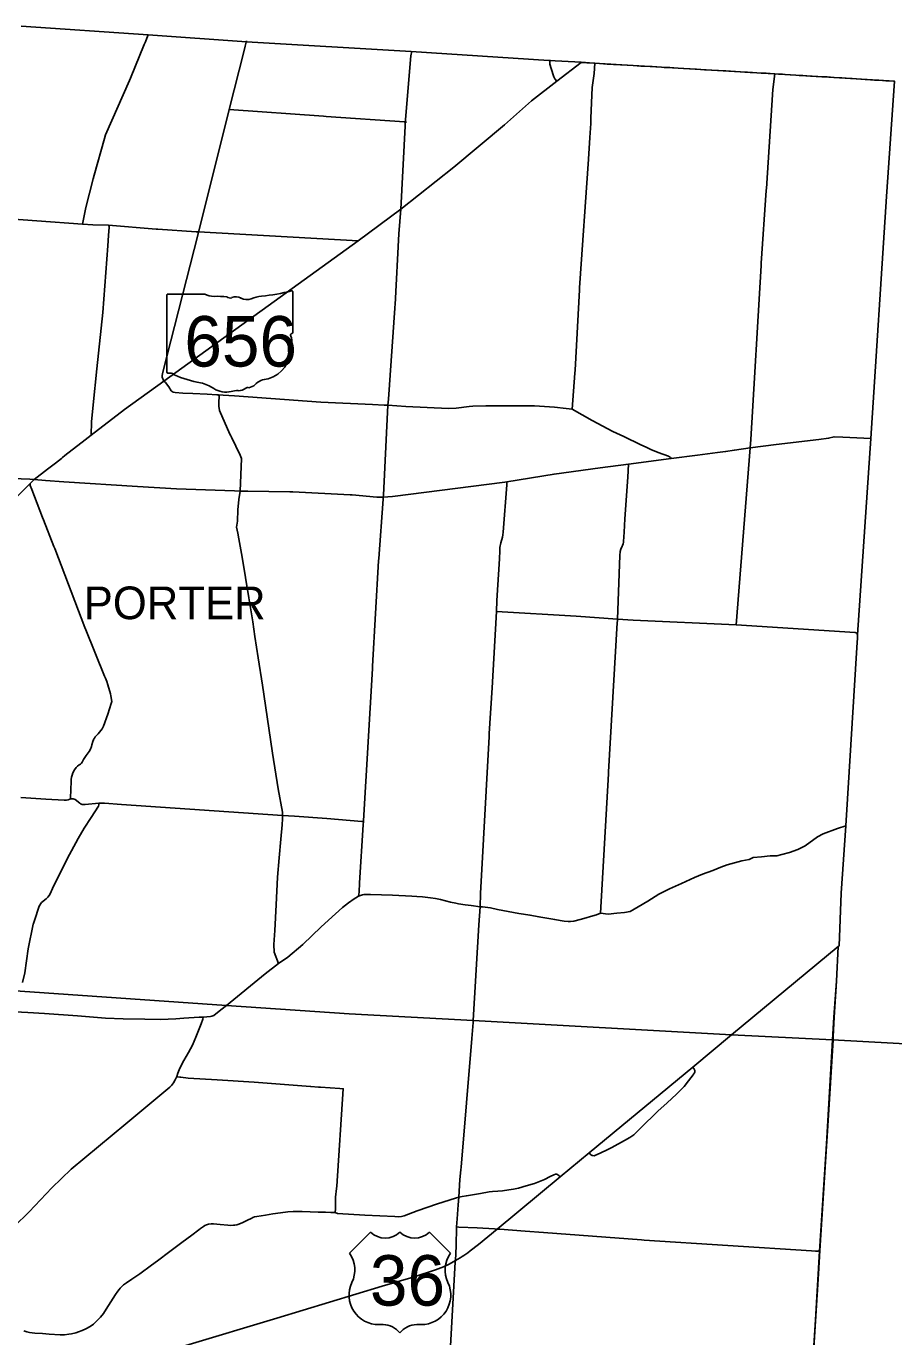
# Model space of a CAD drawing. Extents: x 1729596 to 1925846, y 659247 to 911751.
# Drawn here: x 1876281 to 1900207, y 821273 to 857428 of the extents above; entities that cross this region are included whole.
import ezdxf

# ---------------------------------------------------------------- set-up
doc = ezdxf.new("R2010")
doc.units = 0
for name, color, linetype in [('GM_X_Adjacent_County', 7, 'Continuous'), ('GM_X_County', 7, 'Continuous'), ('GM_X_County_Road', 7, 'Continuous'), ('GM_X_State_Route', 7, 'Continuous'), ('GM_X_State_Shield', 7, 'Continuous'), ('GM_X_Township', 7, 'Continuous'), ('GM_X_Township_Road', 7, 'Continuous'), ('GM_X_Township_Text', 7, 'Continuous'), ('GM_X_US_Route', 7, 'Continuous'), ('GM_X_US_Shield', 7, 'Continuous')]:
    doc.layers.add(name, color=color, linetype=linetype)

msp = doc.modelspace()

# ---------------------------------------------------------------- linework, layer by layer
at = {"layer": 'GM_X_Adjacent_County'}
msp.add_line((1898513, 829466), (1915254, 828516), dxfattribs=at)
at = {"layer": 'GM_X_County'}
msp.add_lwpolyline([(1876143, 857428), (1879641, 857188), (1882352, 856998), (1886895, 856734), (1890695, 856480), (1891588, 856432), (1891937, 856405), (1896895, 856116), (1900228, 855908), (1900008, 852727), (1899571, 846055), (1899210, 840637), (1899208, 840537), (1899202, 840435), (1898887, 835373), (1898754, 833509), (1898698, 832056), (1898677, 832037), (1898625, 831088), (1898557, 830092), (1898513, 829466), (1898352, 826597), (1898155, 823638), (1898045, 821739), (1897825, 818330)], dxfattribs=at)
at = {"layer": 'GM_X_County_Road'}
for points in [[(1878069, 846144), (1878085, 846512), (1878125, 846983), (1878226, 847978), (1878395, 849532), (1878536, 851373), (1878554, 851651), (1878570, 851880), (1878570, 851906), (1878562, 851922), (1878551, 851936), (1878115, 851952), (1877831, 851971), (1877925, 852422), (1878131, 853220), (1878152, 853318), (1878443, 854333), (1878470, 854429), (1879125, 855929), (1879153, 855993), (1879536, 856921), (1879568, 856998), (1879605, 857097), (1879641, 857189)], [(1886129, 844439), (1886132, 844491), (1886249, 846785), (1886257, 846969), (1886270, 847136), (1886449, 849651), (1886451, 849675), (1886456, 849754), (1886558, 851700), (1886613, 852377)], [(1876497, 844924), (1876809, 844899), (1877320, 844863), (1879351, 844730), (1880430, 844669), (1882026, 844608), (1882181, 844601), (1882392, 844602), (1883554, 844583), (1883632, 844581), (1885215, 844502), (1885270, 844499), (1885954, 844440), (1886129, 844439), (1886387, 844458), (1889478, 844848), (1889539, 844855), (1890840, 845073), (1892109, 845243), (1892893, 845346), (1894066, 845501), (1894790, 845594), (1895349, 845664), (1895569, 845695), (1895814, 845736), (1896247, 845793), (1896967, 845887), (1898141, 846028), (1898411, 846062), (1898560, 846100), (1898798, 846088), (1899571, 846055)], [(1883352, 835653), (1883345, 835749), (1883225, 836391), (1883075, 837371), (1882925, 838372), (1882793, 839248), (1882676, 839999), (1882590, 840590), (1882528, 840993), (1882422, 841658), (1882235, 842776), (1882147, 843282), (1882115, 843443), (1882081, 843608), (1882104, 843778), (1882120, 844088), (1882142, 844371), (1882181, 844601)], [(1888604, 829939), (1888609, 830001), (1888760, 832637), (1888800, 833137), (1888812, 833505), (1889049, 837835), (1889053, 837918), (1889133, 839176), (1889247, 841285), (1889264, 841582), (1889332, 842735), (1889339, 842955), (1889347, 843044), (1889371, 843177), (1889414, 843329), (1889428, 843400), (1889436, 843472), (1889534, 844778), (1889539, 844855)], [(1876128, 836148), (1876819, 836105), (1877326, 836075), (1877391, 836079), (1877434, 836089), (1877480, 836104), (1877504, 836111), (1877539, 836118), (1877542, 836118), (1877573, 836116), (1877603, 836108), (1877631, 836094), (1877756, 835993), (1877776, 835979), (1877806, 835965), (1877821, 835960), (1877854, 835956), (1877887, 835957), (1877903, 835960), (1878279, 835990)], [(1883240, 831567), (1883121, 831886), (1883110, 832097), (1883136, 832477), (1883174, 833194), (1883211, 833953), (1883259, 834488), (1883303, 835001), (1883338, 835393), (1883351, 835566), (1883352, 835653)], [(1883240, 831567), (1883496, 831745), (1883911, 832096), (1884413, 832583), (1884807, 832938), (1885003, 833112), (1885166, 833243), (1885326, 833358), (1885368, 833385), (1885446, 833427), (1885524, 833460), (1885556, 833468), (1885599, 833476), (1885624, 833478), (1885649, 833478), (1885778, 833475), (1886380, 833452), (1886918, 833430), (1887051, 833421), (1887207, 833409), (1887432, 833384), (1887568, 833364), (1887708, 833334), (1887981, 833265), (1888133, 833232), (1888203, 833219), (1888385, 833194), (1888553, 833173), (1888800, 833137), (1888866, 833133), (1889085, 833106), (1889281, 833061), (1889870, 832955), (1890175, 832901), (1890421, 832859), (1890857, 832781), (1891011, 832754), (1891116, 832738), (1891228, 832726), (1891289, 832726), (1891379, 832736), (1891557, 832782), (1891660, 832813), (1891907, 832887), (1892010, 832918), (1892122, 832957), (1892327, 832934), (1892566, 832957), (1892784, 832982), (1892937, 833003), (1893157, 833131), (1893427, 833287), (1893731, 833483), (1894025, 833628), (1894350, 833781), (1894712, 833939), (1894934, 834036), (1895214, 834140), (1895437, 834225), (1895608, 834291), (1896021, 834405), (1896215, 834443), (1896330, 834491), (1896557, 834514), (1896797, 834537), (1896986, 834540), (1897122, 834582), (1897333, 834631), (1897563, 834720), (1897761, 834818), (1898107, 835064), (1898263, 835149), (1898656, 835291), (1898887, 835373)], [(1898531, 829465), (1898535, 829554), (1898563, 830092), (1898625, 831088), (1898677, 832037)], [(1881648, 830290), (1881808, 830417), (1882869, 831288), (1883240, 831567)], [(1874959, 823358), (1876327, 824682), (1876365, 824720), (1876987, 825381), (1877524, 825893), (1879029, 827144), (1880240, 828159), (1880290, 828209), (1880342, 828279), (1880387, 828358), (1880432, 828452), (1880464, 828542), (1880520, 828684), (1880625, 828898), (1880689, 829004), (1880756, 829118), (1880864, 829316), (1880962, 829539), (1881103, 829903), (1881150, 830037), (1881159, 830094), (1881361, 830106), (1881400, 830115), (1881455, 830137), (1881648, 830290)], [(1888211, 825123), (1888238, 825608), (1888269, 825875), (1888275, 825951), (1888566, 829499), (1888604, 829939)], [(1897822, 818179), (1897829, 818255), (1897948, 820090), (1898048, 821704), (1898128, 823007), (1898166, 823650), (1898353, 826531), (1898388, 827089), (1898531, 829465)], [(1891807, 826349), (1891855, 826296), (1891892, 826275), (1891910, 826271), (1891947, 826267), (1891967, 826270), (1892112, 826338), (1892322, 826440), (1892434, 826497), (1892779, 826687), (1892926, 826772), (1893037, 826849), (1893103, 826910), (1893327, 827129), (1893595, 827398), (1893703, 827499), (1893960, 827731), (1894216, 827965), (1894365, 828110), (1894427, 828179), (1894548, 828334), (1894670, 828497), (1894687, 828515), (1894710, 828555), (1894718, 828575), (1894723, 828595), (1894722, 828618), (1894713, 828640), (1894693, 828679), (1894662, 828715)], [(1876217, 821438), (1876297, 821406), (1876374, 821389), (1876519, 821376), (1876727, 821364), (1876913, 821349), (1877214, 821328), (1877336, 821330), (1877454, 821342), (1877534, 821356), (1877649, 821382), (1877722, 821406), (1877821, 821445), (1877928, 821496), (1878043, 821558), (1878138, 821626), (1878219, 821701), (1878331, 821818), (1878413, 821920), (1878486, 822032), (1878616, 822239), (1878743, 822436), (1878811, 822535), (1878842, 822578), (1878871, 822613), (1878895, 822642), (1878934, 822678), (1878967, 822704), (1879044, 822758), (1879197, 822860), (1879414, 823008), (1879735, 823245), (1879901, 823370), (1880245, 823625), (1880570, 823871), (1880847, 824079), (1881042, 824227), (1881087, 824259), (1881166, 824319), (1881210, 824345), (1881256, 824365), (1881305, 824380), (1881378, 824389), (1881448, 824388), (1881628, 824373), (1881838, 824352), (1881925, 824346), (1881993, 824349), (1882027, 824352), (1882091, 824364), (1882142, 824378), (1882259, 824424), (1882312, 824450), (1882368, 824481), (1882502, 824549), (1882531, 824563), (1882576, 824578), (1882637, 824590), (1882881, 824632), (1883086, 824662), (1883290, 824696), (1883493, 824720), (1883640, 824734), (1883773, 824733), (1883887, 824727), (1884332, 824715), (1884531, 824707), (1884682, 824698), (1884802, 824698), (1884869, 824677), (1885617, 824633), (1886029, 824607), (1886447, 824588), (1886561, 824584), (1886629, 824591), (1886701, 824609), (1887064, 824744), (1887621, 824941), (1888121, 825102), (1888211, 825123), (1888301, 825141), (1888421, 825162), (1888813, 825227), (1889047, 825270), (1889140, 825279), (1889289, 825293), (1889417, 825300), (1889589, 825323), (1889719, 825344), (1889858, 825376), (1890073, 825441), (1890297, 825503), (1890440, 825558), (1890572, 825616), (1890734, 825693), (1890836, 825744), (1890880, 825758), (1890902, 825760), (1890937, 825746), (1890980, 825715), (1891009, 825686)], [(1888119, 823374), (1888136, 823770), (1888147, 824305), (1888170, 824530), (1888198, 824915), (1888211, 825123)], [(1888147, 824305), (1888213, 824298), (1888717, 824283), (1889192, 824249), (1889265, 824243)], [(1889265, 824243), (1889344, 824238), (1890044, 824187), (1890551, 824150), (1893249, 823947), (1893321, 823942), (1897937, 823643), (1898048, 823639), (1898076, 823638), (1898114, 823638), (1898140, 823641), (1898166, 823650)], [(1887858, 818871), (1888113, 823336), (1888119, 823374)]]:
    msp.add_lwpolyline(points, dxfattribs=at)
at = {"layer": 'GM_X_State_Route'}
for points in [[(1877908, 846019), (1878069, 846144), (1878991, 846854), (1880073, 847637), (1885437, 851504), (1886613, 852377), (1888074, 853536), (1889468, 854711), (1890217, 855366), (1890913, 855912), (1891583, 856425)], [(1875906, 844320), (1876154, 844572), (1876386, 844812), (1876497, 844924), (1876868, 845210), (1877089, 845378), (1877250, 845505), (1877281, 845529), (1877348, 845583), (1877908, 846019)], [(1875906, 844954), (1876379, 844930), (1876497, 844924)]]:
    msp.add_lwpolyline(points, dxfattribs=at)
at = {"layer": 'GM_X_State_Shield'}
for p, q in [((1880157, 850003), (1880157, 847890)), ((1880157, 850003), (1880157, 847890)), ((1881211, 850040), (1880192, 850040)), ((1881211, 850040), (1880192, 850040)), ((1883638, 848987), (1883638, 850092)), ((1883638, 848987), (1883638, 850092)), ((1883637, 848987), (1883638, 848987)), ((1883637, 848987), (1883638, 848987))]:
    msp.add_line(p, q, dxfattribs=at)
for centre, major_axis, start_param, end_param in [((1880197, 850008), (40.3, 0), 1.712693, 3.28349), ((1880197, 850008), (40.3, 0), 1.712693, 3.28349), ((1881453, 850285), (391, 0), 4.042523, 4.731795), ((1881453, 850285), (391, 0), 4.042523, 4.731795), ((1882869, 849394), (743, 0), 1.699011, 2.107814), ((1882869, 849394), (743, 0), 1.699011, 2.107814), ((1882398, 852921), (3691, 0), 4.814394, 5.042369), ((1882398, 852921), (3691, 0), 4.814394, 5.042369), ((1883599, 850097), (38.7, 0), 6.141152, 7.989035), ((1883599, 850097), (38.7, 0), 6.141152, 7.989035), ((1881583, 848853), (1404, 0), 1.404758, 1.657858), ((1881583, 848853), (1404, 0), 1.404758, 1.657858), ((1881902, 850019), (113, 0), 3.836095, 5.185415), ((1881902, 850019), (113, 0), 3.836095, 5.185415), ((1882068, 849775), (235, 0), 0.950623, 2.079405), ((1882068, 849775), (235, 0), 0.950623, 2.079405), ((1882370, 850110), (282, 0), 4.081561, 5.145723), ((1882370, 850110), (282, 0), 4.081561, 5.145723), ((1883629, 848905), (60, 0), 1.883978, 3.671073), ((1883629, 848905), (60, 0), 1.883978, 3.671073), ((1883596, 848982), (41.5, 0), 5.05454, 6.418171), ((1883596, 848982), (41.5, 0), 5.05454, 6.418171), ((1883776, 848524), (262, 0), 2.387724, 3.262537), ((1883776, 848524), (262, 0), 2.387724, 3.262537), ((1883247, 848766), (360, 0), 5.934695, 6.695948), ((1883247, 848766), (360, 0), 5.934695, 6.695948), ((1882605, 848383), (923, 0), 5.101752, 6.440018), ((1882605, 848383), (923, 0), 5.101752, 6.440018), ((1880197, 847885), (40.7, 0), 3.00124, 4.508301), ((1880197, 847885), (40.7, 0), 3.00124, 4.508301), ((1880204, 848102), (310, 0), 4.665946, 4.897461), ((1880204, 848102), (310, 0), 4.665946, 4.897461), ((1880267, 847768), (112, 0), 0.519207, 1.627899), ((1880267, 847768), (112, 0), 0.519207, 1.627899), ((1881680, 849667), (2665, 0), 4.195997, 4.488961), ((1881680, 849667), (2665, 0), 4.195997, 4.488961), ((1880886, 846941), (834, 0), 0.823519, 1.323587), ((1880886, 846941), (834, 0), 0.823519, 1.323587), ((1882387, 847395), (79.4, 0), 1.147584, 2.315152), ((1882387, 847395), (79.4, 0), 1.147584, 2.315152), ((1882353, 847685), (298, 0), 4.937069, 5.64225), ((1882353, 847685), (298, 0), 4.937069, 5.64225), ((1882994, 847297), (506, 0), 1.647645, 2.488434), ((1882994, 847297), (506, 0), 1.647645, 2.488434), ((1881788, 847758), (529, 0), 4.026481, 4.996735), ((1881788, 847758), (529, 0), 4.026481, 4.996735), ((1882093, 847027), (435, 0), 1.495662, 1.94098), ((1882093, 847027), (435, 0), 1.495662, 1.94098), ((1882132, 847599), (282, 0), 4.691044, 5.507374), ((1882132, 847599), (282, 0), 4.691044, 5.507374)]:
    msp.add_ellipse(centre, major_axis=major_axis, ratio=0.8, start_param=start_param, end_param=end_param, dxfattribs=at)
at = {"layer": 'GM_X_Township'}
msp.add_lwpolyline([(1871199, 820179), (1871965, 831096), (1873866, 830983), (1874715, 830911), (1874782, 830900), (1876113, 830808), (1881808, 830417), (1885186, 830186), (1888609, 830001), (1895732, 829600), (1898513, 829466)], dxfattribs=at)
at = {"layer": 'GM_X_Township_Road'}
for points in [[(1881030, 851742), (1881033, 851753), (1881038, 851772), (1881876, 855126), (1882288, 856762), (1882322, 856876), (1882360, 857020)], [(1886743, 854850), (1886885, 856612), (1886918, 856737)], [(1890913, 855912), (1890862, 855972), (1890828, 856035), (1890756, 856263), (1890718, 856382), (1890717, 856500)], [(1891583, 856425), (1891639, 856423), (1891746, 856417), (1891965, 856405)], [(1891854, 854895), (1891886, 855736), (1891944, 856127), (1891965, 856405)], [(1891965, 856405), (1892090, 856398), (1892301, 856385), (1892481, 856374), (1892856, 856351), (1893019, 856342), (1893232, 856329), (1893543, 856312), (1893805, 856297), (1893879, 856293), (1894034, 856284), (1894263, 856272), (1894410, 856264), (1894590, 856253), (1894770, 856241), (1894983, 856228), (1895376, 856205), (1895572, 856194), (1895703, 856186), (1895981, 856169), (1896095, 856161), (1896177, 856156), (1896242, 856153), (1896308, 856149), (1896553, 856136), (1896684, 856128), (1896799, 856122), (1896913, 856115), (1896923, 856115)], [(1896693, 852936), (1896693, 852946), (1896876, 855684), (1896923, 856115)], [(1896923, 856115), (1897028, 856108), (1897142, 856101), (1897208, 856097), (1897503, 856079), (1897601, 856072), (1897699, 856066), (1897780, 856061), (1897911, 856054), (1898222, 856035), (1898370, 856027), (1898550, 856015), (1898713, 856004), (1898778, 856000), (1898893, 855993), (1899057, 855983), (1899416, 855960), (1899563, 855950), (1899678, 855942), (1899792, 855935), (1899988, 855922), (1900186, 855910)], [(1881876, 855126), (1884475, 854944), (1884555, 854939), (1886714, 854786), (1886737, 854784), (1886771, 854782)], [(1886613, 852377), (1886732, 854673), (1886735, 854748), (1886736, 854770), (1886737, 854784), (1886738, 854791), (1886743, 854850)], [(1891340, 846864), (1891414, 847853), (1891419, 847939), (1891537, 850153), (1891540, 850214), (1891785, 853757), (1891824, 854360), (1891848, 854742), (1891854, 854895)], [(1896247, 845793), (1896262, 846026), (1896550, 850831), (1896553, 850892), (1896690, 852894), (1896692, 852927), (1896693, 852936)], [(1875301, 852152), (1877831, 851971)], [(1878551, 851936), (1879863, 851829)], [(1879863, 851829), (1879912, 851825), (1880967, 851757)], [(1880073, 847637), (1880028, 847749), (1880030, 847793), (1880052, 847886), (1881020, 851698), (1881027, 851730), (1881030, 851742)], [(1880967, 851757), (1881014, 851754), (1881019, 851754), (1881033, 851753), (1885437, 851504)], [(1880073, 847637), (1880119, 847597), (1880215, 847475), (1880282, 847373), (1880306, 847346), (1880336, 847332), (1880393, 847320), (1880601, 847305), (1880879, 847291), (1881267, 847277), (1881536, 847259), (1881580, 847257), (1881708, 847250), (1882026, 847230), (1884406, 847060), (1885829, 846989), (1886154, 846974), (1886257, 846969), (1886753, 846940), (1887931, 846886), (1888141, 846889), (1888497, 846936), (1888601, 846948), (1888952, 846957), (1889403, 846957), (1889669, 846954), (1890015, 846956), (1890296, 846958), (1890853, 846915), (1891169, 846885), (1891340, 846864)], [(1882181, 844601), (1882218, 845500), (1882218, 845505), (1882178, 845591), (1881944, 846088), (1881925, 846129), (1881900, 846178), (1881613, 846828), (1881595, 846950), (1881589, 847049), (1881601, 847222), (1881580, 847257)], [(1891340, 846864), (1891616, 846711), (1891890, 846553), (1892461, 846246), (1892758, 846106), (1893234, 845882), (1893382, 845812), (1893507, 845752), (1893710, 845669), (1893997, 845564), (1894023, 845549), (1894046, 845529), (1894066, 845501)], [(1895863, 840910), (1896247, 845793)], [(1892122, 832957), (1892339, 836806), (1892341, 836860), (1892582, 840972), (1892585, 841036), (1892586, 841074), (1892651, 842825), (1892652, 842854), (1892658, 842912), (1892664, 842941), (1892680, 842997), (1892719, 843085), (1892728, 843106), (1892742, 843149), (1892749, 843194), (1892750, 843216), (1892770, 843468), (1892794, 843834), (1892869, 844984), (1892893, 845346)], [(1878444, 839494), (1877928, 840772), (1877899, 840844), (1877069, 843015), (1877046, 843075), (1876757, 843812), (1876734, 843872), (1876436, 844644), (1876389, 844761), (1876386, 844812)], [(1885446, 833427), (1885462, 833535), (1885473, 833796), (1885574, 835394), (1885580, 835487), (1885580, 835490), (1885581, 835505), (1885831, 839707), (1885835, 839776), (1885999, 842676), (1886002, 842745), (1886125, 844378), (1886129, 844439)], [(1889247, 841285), (1891451, 841156), (1892586, 841074), (1893022, 841042), (1895863, 840910), (1899143, 840698), (1899170, 840695), (1899188, 840685), (1899198, 840677), (1899202, 840668), (1899210, 840637), (1899208, 840537)], [(1877504, 836111), (1877505, 836183), (1877512, 836312), (1877521, 836644), (1877530, 836707), (1877546, 836769), (1877568, 836829), (1877610, 836910), (1877659, 836975), (1877699, 837015), (1877743, 837051), (1877776, 837074), (1877803, 837097), (1877825, 837126), (1877835, 837141), (1877864, 837196), (1877880, 837227), (1877896, 837256), (1877932, 837309), (1877992, 837382), (1878020, 837419), (1878051, 837481), (1878079, 837553), (1878089, 837602), (1878118, 837696), (1878135, 837742), (1878140, 837754), (1878161, 837789), (1878186, 837820), (1878262, 837909), (1878336, 837999), (1878371, 838044), (1878412, 838119), (1878530, 838451), (1878625, 838740), (1878645, 838799), (1878617, 838955), (1878607, 839009), (1878529, 839261), (1878501, 839352), (1878466, 839439), (1878444, 839494)], [(1876176, 831049), (1876244, 831313), (1876339, 831976), (1876476, 832658), (1876479, 832675), (1876506, 832758), (1876634, 833154), (1876703, 833255), (1876835, 833358), (1876875, 833401), (1876911, 833448), (1876937, 833491), (1877010, 833643), (1877414, 834454), (1877715, 835018), (1877883, 835308), (1878069, 835602), (1878276, 835912), (1878286, 835945), (1878286, 835969), (1878279, 835990)], [(1878279, 835990), (1878360, 835995), (1878441, 835994), (1878907, 835961), (1883352, 835653)], [(1883352, 835653), (1883676, 835633), (1884568, 835572), (1885540, 835488), (1885580, 835487), (1885592, 835487)], [(1875972, 830241), (1876325, 830221), (1876782, 830190), (1877695, 830124), (1878463, 830066), (1878952, 830045), (1879551, 830034), (1879982, 830022), (1880411, 830048), (1880624, 830061), (1881052, 830089), (1881159, 830094)], [(1880432, 828452), (1880452, 828445), (1880516, 828438), (1880549, 828431), (1880745, 828411), (1881545, 828362), (1882567, 828296), (1884124, 828178)], [(1884124, 828178), (1884130, 828177), (1884339, 828164), (1884399, 828160), (1884926, 828125), (1885023, 828118), (1884844, 825432), (1884839, 825362), (1884813, 825123), (1884810, 824800), (1884802, 824698)]]:
    msp.add_lwpolyline(points, dxfattribs=at)
at = {"layer": 'GM_X_US_Route'}
msp.add_lwpolyline([(1880687, 821035), (1883192, 821790), (1886098, 822667), (1886884, 822903), (1887402, 823063), (1887564, 823117), (1887787, 823203), (1887941, 823279), (1888119, 823374), (1888248, 823452), (1888302, 823484), (1888354, 823517), (1888407, 823552), (1888458, 823588), (1888528, 823642), (1888751, 823815), (1889265, 824243), (1891009, 825686), (1891807, 826349), (1894662, 828715), (1895732, 829600), (1898677, 832037), (1898698, 832056)], dxfattribs=at)
at = {"layer": 'GM_X_US_Shield'}
for p, q in [((1885775, 824163), (1885195, 823583)), ((1885775, 824163), (1885195, 823583)), ((1887980, 823583), (1887400, 824163)), ((1887980, 823583), (1887400, 824163)), ((1886007, 821611), (1886123, 821611)), ((1886007, 821611), (1886123, 821611)), ((1887051, 821611), (1887167, 821611)), ((1887051, 821611), (1887167, 821611))]:
    msp.add_line(p, q, dxfattribs=at)
for centre, radius, start, end in [((1886181, 824577), 580, 225.573, 314.427), ((1886181, 824577), 580, 225.573, 314.427), ((1886993, 824577), 580, 225.573, 314.427), ((1886993, 824577), 580, 225.573, 314.427), ((1884530, 823117), 812, 334.5471, 35.0009), ((1884530, 823117), 812, 334.5471, 35.0009), ((1888645, 823117), 812, 144.9991, 205.4529), ((1888645, 823117), 812, 144.9991, 205.4529), ((1885998, 822423), 812, 154.8319, 270.6383), ((1885998, 822423), 812, 154.8319, 270.6383), ((1887177, 822423), 812, 269.3617, 25.1681), ((1887177, 822423), 812, 269.3617, 25.1681), ((1886123, 821030), 580, 36.8699, 90), ((1886123, 821030), 580, 36.8699, 90), ((1887051, 821030), 580, 90, 143.1301), ((1887051, 821030), 580, 90, 143.1301)]:
    msp.add_arc(centre, radius, start, end, dxfattribs=at)

# ---------------------------------------------------------------- texts
at = {"layer": 'GM_X_State_Shield'}
msp.add_text('656', height=1392.2, dxfattribs=at).set_placement((1880642, 848039))
msp.add_text('656', height=1392.2, dxfattribs=at).set_placement((1880642, 848039))
at = {"layer": 'GM_X_Township_Text'}
msp.add_text('PORTER', height=900, rotation=0, dxfattribs=at).set_placement((1877867, 841070))
at = {"layer": 'GM_X_US_Shield'}
msp.add_text('36', height=1392.2, dxfattribs=at).set_placement((1885760, 822133))
msp.add_text('36', height=1392.2, dxfattribs=at).set_placement((1885760, 822133))

doc.saveas('drawing.dxf')
